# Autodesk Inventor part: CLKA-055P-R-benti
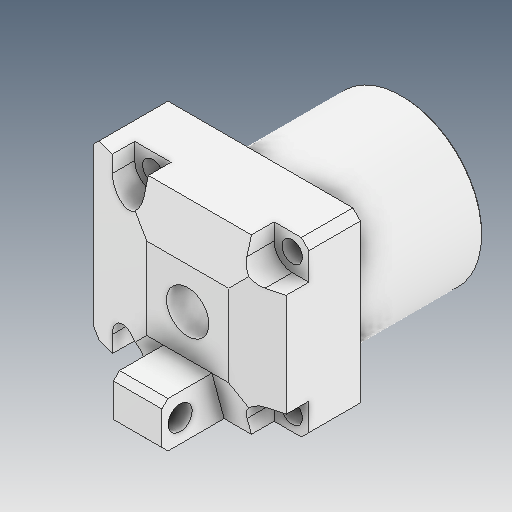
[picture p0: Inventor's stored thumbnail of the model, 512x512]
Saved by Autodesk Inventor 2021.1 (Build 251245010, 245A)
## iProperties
Created: 2021-06
Part Number: CLKA-055P-R-benti
Material: Ogólny
Document SubType Name: Modeling
Designer: user
Density: 1 g/cm^3
Appearance: Domyślna
Author: user
Revision Number: ÈÎºÎ
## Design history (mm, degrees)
feature "ÇÐ³ý-Ðý×ª5"
node "Bryła1"
